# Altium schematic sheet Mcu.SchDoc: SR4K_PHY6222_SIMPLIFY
size A4; Revision: V1.2; SheetNumber: 2; SheetTotal: 5
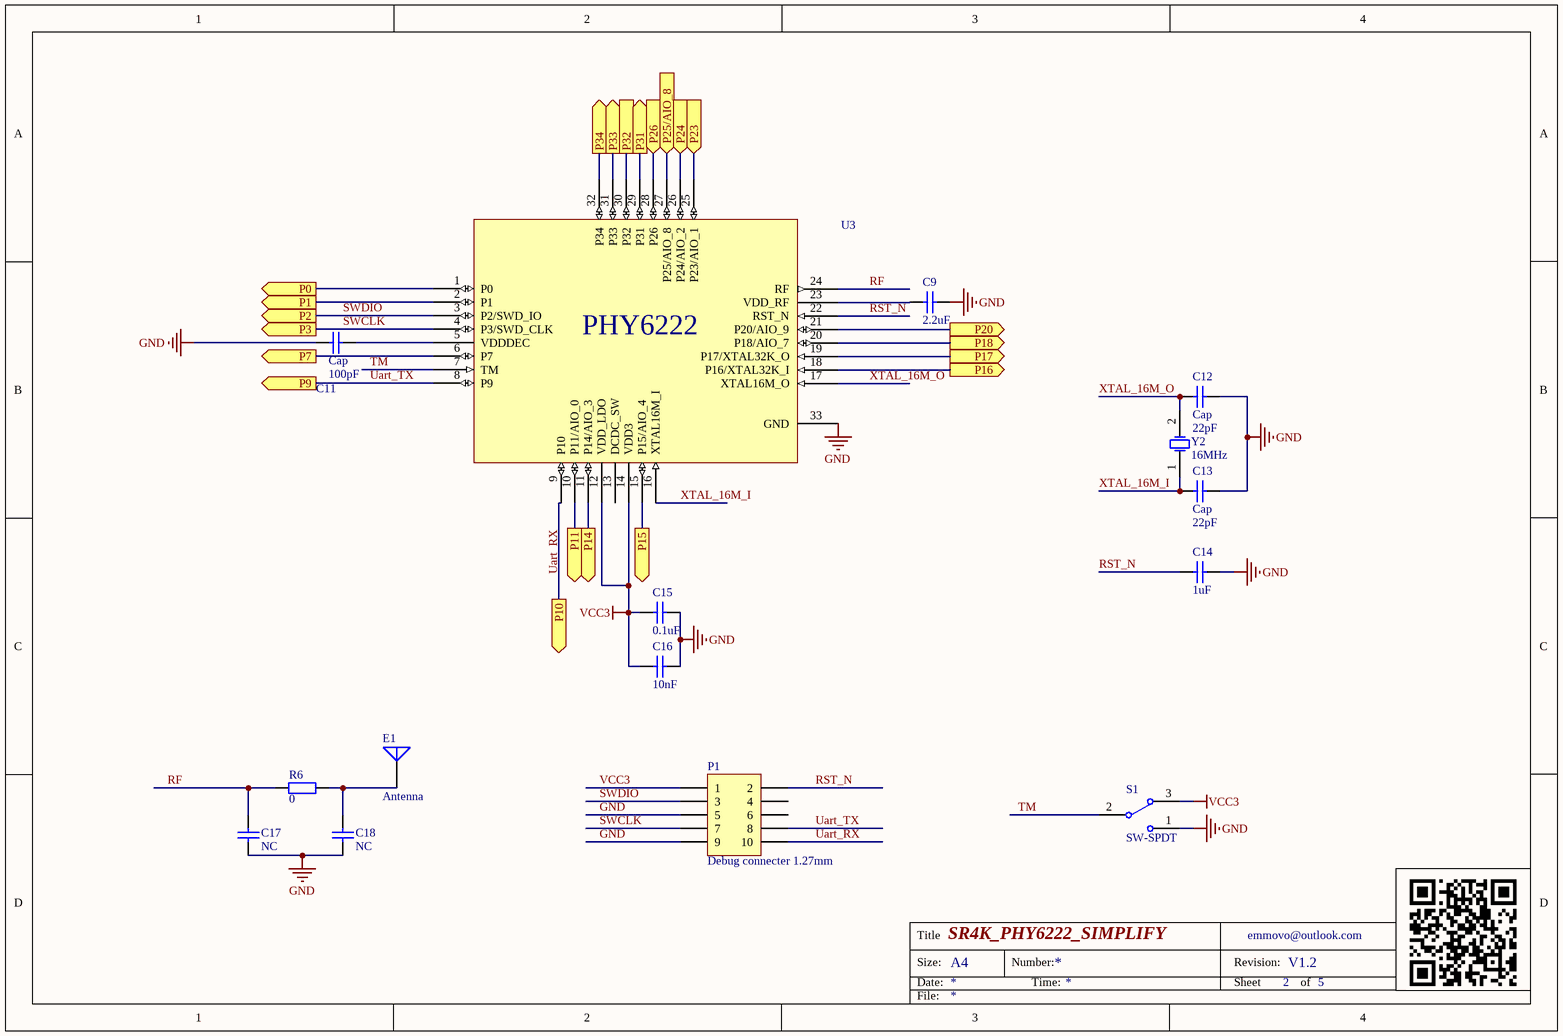
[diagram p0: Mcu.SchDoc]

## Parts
C9  value 2.2uF  (hidden comment: Cap)
C11  Cap  value 100pF
C12  Cap  value 22pF
C13  Cap  value 22pF
C14  value 1uF  (hidden comment: Cap)
C15  value 0.1uF  (hidden comment: Cap)
C16  value 10nF  (hidden comment: Cap)
C17  value NC  (hidden comment: Cap)
C18  value NC  (hidden comment: Cap)
E1  Antenna  [PIN1]
P1  Debug connecter 1.27mm
R6  0
S1  SW-SPDT
U3  U*  (value not drawn)
Y2  16MHz

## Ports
P0 (out), P1 (out), P2 (out), P3 (out), P7 (out), P9 (out), P10 (out), P11 (out), P14 (out), P15 (out), P16 (out), P17 (out), P18 (out), P20 (out), P23 (in), P24 (in), P25/AIO_8 (in), P26 (in), P31 (out), P32, P33 (out), P34 (out)

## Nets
GND: C9.2 C11.1 C12.1 C13.1 C14.2 C15.2 C16.2 C17.2 C18.2 P1.5 P1.9 S1.1 U3.33(GND)
VCC3: P1.1 S1.3
P0: U3.1(P0) ; port P0
P1: U3.2(P1) ; port P1
P7: U3.6(P7) ; port P7
P10: U3.9(P10) ; port P10
P11: U3.10(P11/AIO_0) ; port P11
P14: U3.11(P14/AIO_3) ; port P14
P15: U3.15(P15/AIO_4) ; port P15
P16: U3.18(P16/XTAL32K_I) ; port P16
P17: U3.19(P17/XTAL32K_O) ; port P17
P18: U3.20(P18/AIO_7) ; port P18
P20: U3.21(P20/AIO_9) ; port P20
P23: U3.25(P23/AIO_1) ; port P23
P24: U3.26(P24/AIO_2) ; port P24
P25/AIO_8: U3.27(P25/AIO_8) ; port P25/AIO_8
P26: U3.28(P26) ; port P26
P31: U3.29(P31) ; port P31
P32: U3.30(P32) ; port P32
P33: U3.31(P33) ; port P33
P34: U3.32(P34) ; port P34
RF: C17.1 R6.2 U3.24(RF)
RST_N: C14.1 P1.2 U3.22(RST_N)
SWCLK: P1.7 U3.4(P3/SWD_CLK) ; port P3
SWDIO: P1.3 U3.3(P2/SWD_IO) ; port P2
TM: S1.2 U3.7(TM)
Uart_RX: P1.10
Uart_TX: P1.8 U3.8(P9) ; port P9
XTAL_16M_I: C13.2 U3.16(XTAL16M_I) Y2.1(OSC1)
XTAL_16M_O: C12.2 U3.17(XTAL16M_O) Y2.2(OSC2)
NetC9_1: C9.1 U3.23(VDD_RF)
NetC11_2: C11.2 U3.5(VDDDEC)
NetC15_1: C15.1 C16.1 U3.12(VDD_LDO) U3.14(VDD3)
NetC18_1: C18.1 E1.1(A) R6.1

Not connected (* = marked no-connect by the designer): P1 4 6; U3 13(DCDC_SW)

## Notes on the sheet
- Labels drawn without touching a wire or pin: Uart_RX, VCC3

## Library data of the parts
C9 C11-C18 = Cap: Capacitor
E1 = Antenna: Generic Antenna
P1 = Header 5X2: Header, 5-Pin, Dual row
R6 = Res2: Resistor
S1 = SW-SPDT: SPDT Subminiature Toggle Switch, Right Angle Mounting, Vertical Actuation
U3 = PHY6222
Y2 = XTAL: Crystal Oscillator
